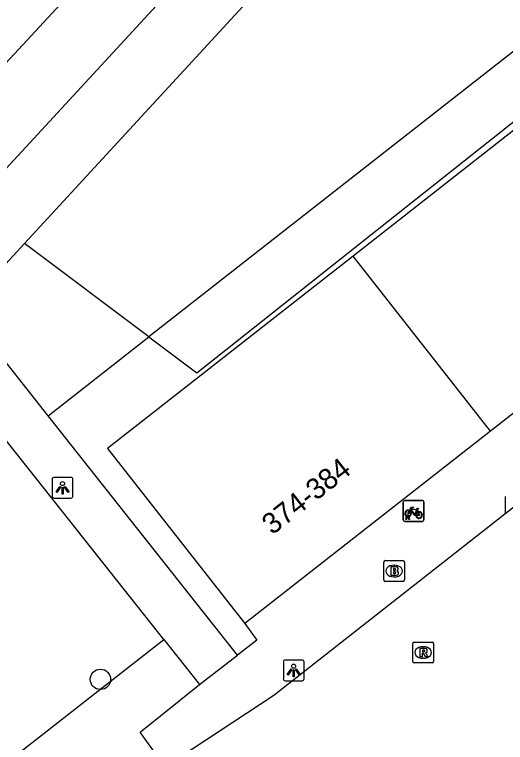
# Model space of a CAD drawing. Extents: x 159222 to 160346, y 381249 to 382166.
# Drawn here: x 159674.12 to 159697.72, y 381652.7 to 381687.69 of the extents above; entities that cross this region are included whole.
import ezdxf

# ---------------------------------------------------------------- set-up
doc = ezdxf.new("R2010")
doc.units = 0
for name, color, linetype in [('IMGEO_Boom', 7, 'Continuous'), ('IMGEO_Brandkraan', 7, 'Continuous'), ('IMGEO_Fietsenrek', 7, 'Continuous'), ('IMGEO_Fietspad_gesloten', 7, 'Continuous'), ('IMGEO_Groenvoorziening', 7, 'Continuous'), ('IMGEO_Haag', 7, 'Continuous'), ('IMGEO_Kolk', 7, 'Continuous'), ('IMGEO_Lichtpunt', 7, 'Continuous'), ('IMGEO_Pand', 7, 'Continuous'), ('IMGEO_Pand_nummerreeks', 7, 'Continuous'), ('IMGEO_Rijbaan_lokaal_open', 7, 'Continuous'), ('IMGEO_Rioolput', 7, 'Continuous'), ('IMGEO_Voetpad_open', 7, 'Continuous')]:
    doc.layers.add(name, color=color, linetype=linetype)

msp = doc.modelspace()

# ---------------------------------------------------------------- linework, layer by layer
at = {"layer": 'IMGEO_Boom'}
msp.add_circle((159678.244, 381655.736), 0.489, dxfattribs=at)
at = {"layer": 'IMGEO_Brandkraan'}
for p, q in [((159691.863, 381660.516), (159691.863, 381661.368)), ((159691.938, 381661.442), (159692.79, 381661.442)), ((159692.351, 381661.222), (159692.376, 381661.222)), ((159692.864, 381661.368), (159692.864, 381660.516)), ((159692.374, 381660.662), (159692.349, 381660.662)), ((159692.79, 381660.442), (159691.938, 381660.442))]:
    msp.add_line(p, q, dxfattribs=at)
for points in [[(159691.863, 381660.516), (159691.863, 381661.368)], [(159691.938, 381661.442), (159692.79, 381661.442)], [(159692.864, 381661.368), (159692.864, 381660.516)], [(159692.211, 381661.142), (159692.211, 381660.742), (159692.424, 381660.742)], [(159692.442, 381661.142), (159692.211, 381661.142)], [(159692.39, 381661.061), (159692.336, 381661.061), (159692.336, 381660.985)], [(159692.336, 381660.985), (159692.389, 381660.985)], [(159692.398, 381660.909), (159692.336, 381660.909), (159692.336, 381660.828)], [(159692.336, 381660.828), (159692.398, 381660.828)], [(159692.79, 381660.442), (159691.938, 381660.442)]]:
    msp.add_lwpolyline(points, dxfattribs=at)
for centre, radius, start, end in [((159691.94, 381661.366), 0.0765, 91.552, 178.448), ((159691.94, 381661.366), 0.0765, 91.552, 178.448), ((159692.788, 381661.366), 0.0765, 1.552, 88.448), ((159692.788, 381661.366), 0.0765, 1.552, 88.448), ((159692.391, 381661.023), 0.0379, 267.8285, 90.9355), ((159692.399, 381660.868), 0.0404, 269.8759, 90.5077), ((159692.446, 381660.997), 0.145, 59.4692, 91.5367), ((159692.471, 381661.044), 0.0922, 285.5137, 58.1501), ((159692.476, 381660.852), 0.105, 301.3115, 78.989), ((159691.94, 381660.518), 0.0765, 181.552, 268.448), ((159691.94, 381660.518), 0.0765, 181.552, 268.448), ((159692.43, 381660.993), 0.251, 268.6676, 293.5347), ((159692.788, 381660.518), 0.0765, 271.552, 358.448), ((159692.788, 381660.518), 0.0765, 271.552, 358.448)]:
    msp.add_arc(centre, radius, start, end, dxfattribs=at)
for centre, major_axis, ratio, start_param, end_param in [((159692.35, 381660.942), (-0.387, 0.002), 0.722429, 4.712389, 7.853982), ((159692.375, 381660.942), (-0.39, 0.002), 0.717154, 1.570796, 4.712389)]:
    msp.add_ellipse(centre, major_axis=major_axis, ratio=ratio, start_param=start_param, end_param=end_param, dxfattribs=at)
at = {"layer": 'IMGEO_Fietsenrek'}
for p, q in [((159692.873, 381664.329), (159693.714, 381664.329)), ((159693.714, 381664.329), (159692.873, 381664.329)), ((159692.798, 381663.404), (159692.798, 381664.245)), ((159692.798, 381664.245), (159692.798, 381663.404)), ((159693.798, 381664.254), (159693.798, 381663.413)), ((159693.798, 381663.413), (159693.798, 381664.254)), ((159693.485, 381663.878), (159693.521, 381663.783)), ((159693.723, 381663.329), (159692.882, 381663.329)), ((159692.882, 381663.329), (159693.723, 381663.329)), ((159692.925, 381663.413), (159692.964, 381663.573)), ((159692.959, 381663.413), (159692.925, 381663.413)), ((159692.994, 381663.561), (159692.959, 381663.413)), ((159693.036, 381663.585), (159693.035, 381663.589)), ((159693.077, 381663.413), (159693.043, 381663.555)), ((159693.067, 381663.596), (159693.068, 381663.589)), ((159693.075, 381663.559), (159693.11, 381663.413)), ((159693.11, 381663.413), (159693.077, 381663.413))]:
    msp.add_line(p, q, dxfattribs=at)
for points in [[(159693.111, 381663.855), (159693.206, 381664.019), (159693.292, 381664.005), (159693.294, 381663.996), (159693.238, 381663.985), (159693.211, 381663.94), (159693.467, 381663.899)], [(159693.467, 381663.899), (159693.492, 381663.948), (159693.486, 381663.952), (159693.463, 381663.956), (159693.451, 381663.963), (159693.45, 381663.966), (159693.452, 381663.971), (159693.547, 381663.956), (159693.549, 381663.946), (159693.539, 381663.933), (159693.527, 381663.927), (159693.513, 381663.933), (159693.485, 381663.878)], [(159693.132, 381663.803), (159693.08, 381663.713), (159693.04, 381663.688), (159693.041, 381663.735), (159693.096, 381663.829)], [(159693.407, 381663.611), (159693.357, 381663.611), (159693.166, 381663.862), (159693.147, 381663.83)], [(159693.454, 381663.874), (159693.197, 381663.915), (159693.18, 381663.886), (159693.347, 381663.666), (159693.454, 381663.874)], [(159693.502, 381663.776), (159693.472, 381663.853), (159693.363, 381663.635), (159693.406, 381663.635)], [(159693.436, 381663.635), (159693.556, 381663.634), (159693.512, 381663.748)], [(159693.532, 381663.755), (159693.587, 381663.61), (159693.437, 381663.61)]]:
    msp.add_lwpolyline(points, dxfattribs=at)
for centre, radius, start, end in [((159692.876, 381664.251), 0.0779, 92.4484, 184.2845), ((159692.876, 381664.251), 0.0779, 92.4484, 184.2845), ((159693.72, 381664.251), 0.0779, 2.4484, 94.2845), ((159693.72, 381664.251), 0.0779, 2.4484, 94.2845), ((159693.038, 381663.714), 0.159, 62.6766, 242.1369), ((159693.038, 381663.714), 0.129, 63.3192, 238.903), ((159693.018, 381663.585), 0.0499, 12.8025, 158.6934), ((159693.018, 381663.585), 0.0174, 12.8025, 163.4502), ((159693.038, 381663.714), 0.129, 283.6043, 43.4302), ((159693.038, 381663.714), 0.159, 283.5766, 46.6042), ((159693.565, 381663.63), 0.159, 113.3408, 178.3217), ((159693.565, 381663.63), 0.159, 187.0065, 105.7708), ((159693.565, 381663.63), 0.129, 113.923, 177.9556), ((159693.565, 381663.63), 0.129, 188.6715, 104.5883), ((159692.876, 381663.407), 0.0779, 182.4484, 274.2845), ((159692.876, 381663.407), 0.0779, 182.4484, 274.2845), ((159693.038, 381663.714), 0.159, 253.9967, 271.7867), ((159693.038, 381663.714), 0.129, 253.415, 269.0204), ((159693.72, 381663.407), 0.0779, 272.4484, 4.2845), ((159693.72, 381663.407), 0.0779, 272.4484, 4.2845)]:
    msp.add_arc(centre, radius, start, end, dxfattribs=at)
at = {"layer": 'IMGEO_Fietspad_gesloten'}
msp.add_lwpolyline([(159627.95, 381634.279), (159632.567, 381639.362), (159637.494, 381645.52), (159642.695, 381651.795), (159649.844, 381659.632), (159712.278, 381726.997), (159749.294, 381767.255), (159766.48, 381785.868)], dxfattribs=at)
at = {"layer": 'IMGEO_Groenvoorziening'}
for points in [[(159719.818, 381702.922), (159680.577, 381672.195)], [(159680.577, 381672.195), (159674.596, 381676.692)], [(159671.617, 381650.084), (159681.285, 381657.655)]]:
    msp.add_lwpolyline(points, dxfattribs=at)
at = {"layer": 'IMGEO_Haag'}
for points in [[(159680.577, 381672.195), (159682.88, 381670.464), (159720.432, 381700.252), (159719.818, 381702.922)], [(159675.736, 381668.404), (159680.577, 381672.195)]]:
    msp.add_lwpolyline(points, dxfattribs=at)
at = {"layer": 'IMGEO_Kolk'}
msp.add_line((159697.717, 381663.677), (159697.717, 381664.529), dxfattribs=at)
msp.add_lwpolyline([(159697.717, 381663.677), (159697.717, 381664.529)], dxfattribs=at)
at = {"layer": 'IMGEO_Lichtpunt'}
for p, q in [((159676.825, 381665.443), (159676.017, 381665.443)), ((159676.825, 381665.443), (159676.017, 381665.443)), ((159675.923, 381665.348), (159675.923, 381664.541)), ((159675.923, 381665.348), (159675.923, 381664.541)), ((159676.919, 381664.541), (159676.919, 381665.348)), ((159676.919, 381664.541), (159676.919, 381665.348)), ((159676.017, 381664.447), (159676.825, 381664.447)), ((159676.017, 381664.447), (159676.825, 381664.447)), ((159687.941, 381656.666), (159687.133, 381656.666)), ((159687.941, 381656.666), (159687.133, 381656.666)), ((159687.039, 381656.571), (159687.039, 381655.764)), ((159687.039, 381656.571), (159687.039, 381655.764)), ((159688.035, 381655.764), (159688.035, 381656.571)), ((159688.035, 381655.764), (159688.035, 381656.571)), ((159687.133, 381655.67), (159687.941, 381655.67)), ((159687.133, 381655.67), (159687.941, 381655.67))]:
    msp.add_line(p, q, dxfattribs=at)
for points in [[(159676.297, 381665.012), (159676.336, 381664.984), (159676.148, 381664.722), (159676.11, 381664.749), (159676.297, 381665.012)], [(159676.509, 381664.984), (159676.547, 381665.011), (159676.734, 381664.749), (159676.695, 381664.721), (159676.509, 381664.984)], [(159676.399, 381664.964), (159676.446, 381664.964), (159676.446, 381664.642), (159676.399, 381664.642), (159676.399, 381664.964)], [(159687.413, 381656.235), (159687.452, 381656.207), (159687.264, 381655.945), (159687.226, 381655.972), (159687.413, 381656.235)], [(159687.515, 381656.187), (159687.562, 381656.187), (159687.562, 381655.865), (159687.515, 381655.865), (159687.515, 381656.187)], [(159687.625, 381656.207), (159687.663, 381656.234), (159687.85, 381655.972), (159687.811, 381655.944), (159687.625, 381656.207)]]:
    msp.add_lwpolyline(points, dxfattribs=at)
for centre in [(159676.422, 381665.146), (159687.538, 381656.369)]:
    msp.add_circle(centre, 0.0994, dxfattribs=at)
for centre, start, end in [((159676.017, 381665.348), 90, 180), ((159676.017, 381665.348), 90, 180), ((159676.825, 381665.348), 0, 90), ((159676.825, 381665.348), 0, 90), ((159676.017, 381664.541), 180, 270), ((159676.017, 381664.541), 180, 270), ((159676.825, 381664.541), 270, 0), ((159676.825, 381664.541), 270, 360), ((159687.133, 381656.571), 90, 180), ((159687.133, 381656.571), 90, 180), ((159687.941, 381656.571), 0, 90), ((159687.941, 381656.571), 0, 90), ((159687.133, 381655.764), 180, 270), ((159687.133, 381655.764), 180, 270), ((159687.941, 381655.764), 270, 0), ((159687.941, 381655.764), 270, 360)]:
    msp.add_arc(centre, 0.0946, start, end, dxfattribs=at)
at = {"layer": 'IMGEO_Pand'}
for points in [[(159702.212, 381685.331), (159690.401, 381676.084)], [(159708.808, 381676.909), (159696.998, 381667.661)], [(159690.401, 381676.084), (159678.59, 381666.838), (159685.188, 381658.413)], [(159696.998, 381667.661), (159690.401, 381676.084)], [(159696.998, 381667.661), (159685.188, 381658.413)]]:
    msp.add_lwpolyline(points, dxfattribs=at)
at = {"layer": 'IMGEO_Rijbaan_lokaal_open'}
msp.add_lwpolyline([(159681.38, 381651.547), (159686.578, 381654.975), (159698.504, 381664.326), (159725.995, 381685.842), (159726.077, 381685.887), (159726.578, 381686.129), (159727.1, 381686.326), (159727.636, 381686.475), (159728.184, 381686.575), (159728.739, 381686.627), (159729.296, 381686.628), (159729.85, 381686.58), (159730.399, 381686.482), (159730.936, 381686.336), (159731.459, 381686.142), (159731.961, 381685.903), (159732.441, 381685.619), (159732.893, 381685.294), (159765.564, 381655.029), (159765.97, 381654.692), (159766.405, 381654.392), (159766.864, 381654.132), (159767.345, 381653.914), (159767.844, 381653.74)], dxfattribs=at)
at = {"layer": 'IMGEO_Rioolput'}
for p, q in [((159693.261, 381656.601), (159693.261, 381657.453)), ((159693.336, 381657.527), (159694.188, 381657.527)), ((159693.749, 381657.307), (159693.774, 381657.307)), ((159694.262, 381657.453), (159694.262, 381656.601)), ((159693.772, 381656.747), (159693.747, 381656.747)), ((159694.188, 381656.527), (159693.336, 381656.527))]:
    msp.add_line(p, q, dxfattribs=at)
for points in [[(159693.261, 381656.601), (159693.261, 381657.453)], [(159693.336, 381657.527), (159694.188, 381657.527)], [(159694.262, 381657.453), (159694.262, 381656.601)], [(159693.85, 381657.225), (159693.598, 381657.227), (159693.598, 381656.827)], [(159693.598, 381656.827), (159693.722, 381656.827), (159693.722, 381656.989), (159693.733, 381656.989)], [(159693.776, 381657.146), (159693.722, 381657.146), (159693.722, 381657.065)], [(159693.722, 381657.065), (159693.774, 381657.065)], [(159693.78, 381656.96), (159693.851, 381656.827), (159693.991, 381656.827), (159693.926, 381656.953)], [(159694.188, 381656.527), (159693.336, 381656.527)]]:
    msp.add_lwpolyline(points, dxfattribs=at)
for centre, radius, start, end in [((159693.338, 381657.451), 0.0765, 91.552, 178.448), ((159693.338, 381657.451), 0.0765, 91.552, 178.448), ((159694.186, 381657.451), 0.0765, 1.552, 88.448), ((159694.186, 381657.451), 0.0765, 1.552, 88.448), ((159693.732, 381656.936), 0.0533, 26.0293, 88.6989), ((159693.758, 381657.254), 0.19, 274.7715, 282.9687), ((159693.782, 381657.05), 0.0964, 77.0061, 93.1865), ((159693.796, 381657.107), 0.0378, 276.6634, 79.6772), ((159693.849, 381657.115), 0.109, 350.3612, 89.416), ((159693.847, 381657.115), 0.112, 277.5842, 350.9817), ((159693.831, 381656.9), 0.108, 29.5134, 73.7905), ((159693.338, 381656.603), 0.0765, 181.552, 268.448), ((159693.338, 381656.603), 0.0765, 181.552, 268.448), ((159694.186, 381656.603), 0.0765, 271.552, 358.448), ((159694.186, 381656.603), 0.0765, 271.552, 358.448)]:
    msp.add_arc(centre, radius, start, end, dxfattribs=at)
for centre, major_axis, ratio, start_param, end_param in [((159693.748, 381657.027), (-0.387, 0.002), 0.722429, 4.712389, 7.853982), ((159693.773, 381657.027), (-0.39, 0.002), 0.717154, 1.570796, 4.712389)]:
    msp.add_ellipse(centre, major_axis=major_axis, ratio=ratio, start_param=start_param, end_param=end_param, dxfattribs=at)
at = {"layer": 'IMGEO_Voetpad_open'}
for points in [[(159768.968, 381783.54), (159738.017, 381750), (159653.897, 381658.843), (159629.643, 381632.69)], [(159674.596, 381676.692), (159715.613, 381721.211)], [(159671.682, 381673.529), (159674.596, 381676.692)], [(159675.736, 381668.404), (159671.682, 381673.529)], [(159684.834, 381656.905), (159675.736, 381668.404)], [(159681.285, 381657.655), (159673.216, 381667.826)], [(159685.188, 381658.413), (159685.759, 381657.626), (159684.834, 381656.905)], [(159681.285, 381657.655), (159683.008, 381655.483)], [(159683.008, 381655.483), (159683.301, 381655.718), (159684.834, 381656.905)], [(159681.011, 381652.018), (159680.162, 381653.201), (159683.008, 381655.483)]]:
    msp.add_lwpolyline(points, dxfattribs=at)

# ---------------------------------------------------------------- texts
at = {"layer": 'IMGEO_Pand_nummerreeks'}
msp.add_text('374-384', height=1, rotation=38.0641, dxfattribs=at).set_placement((159686.509, 381662.648))

doc.saveas('drawing.dxf')
